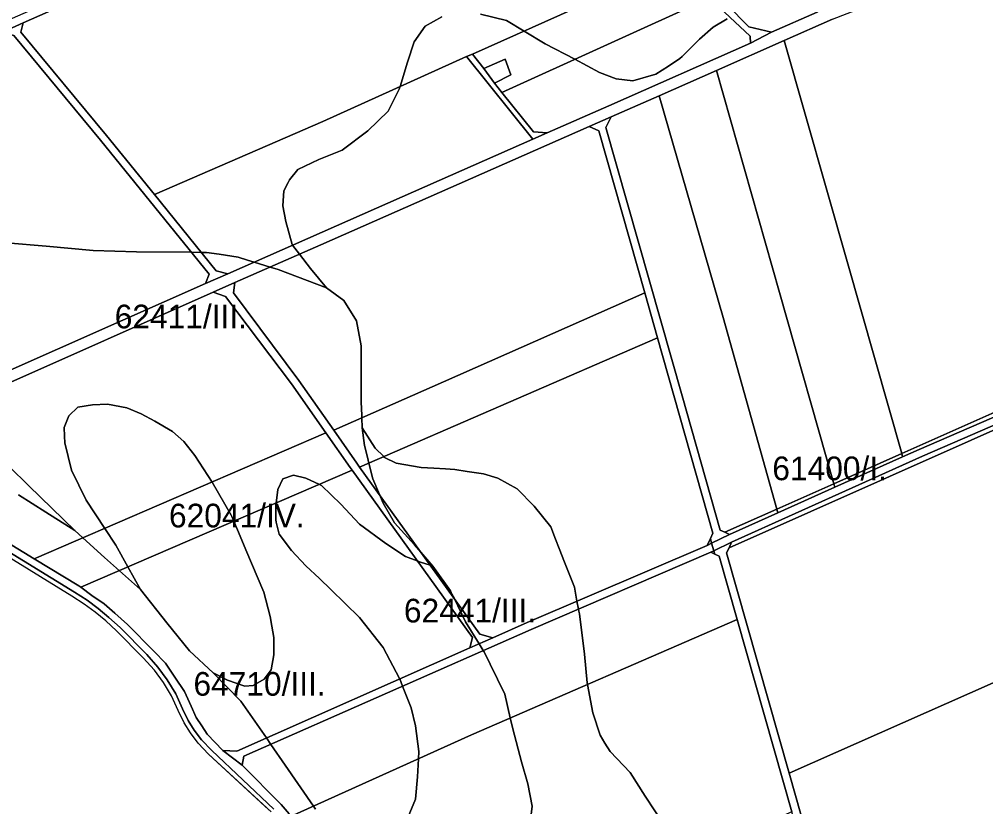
# Model space of a CAD drawing. Extents: x -522079 to -518792, y -1142400 to -1139961.
# Drawn here: x -521597 to -520985, y -1141508 to -1141010 of the extents above; entities that cross this region are included whole.
import ezdxf

# ---------------------------------------------------------------- set-up
doc = ezdxf.new("R2010")
doc.units = 0
for name, color, linetype in [('Hranice parcel', 7, 'Continuous'), ('Parcelní čísla', 7, 'Continuous'), ('Vnitřní kresba', 7, 'Continuous'), ('Značky bodu BP', 7, 'Continuous'), ('Značky budov', 7, 'Continuous')]:
    doc.layers.add(name, color=color, linetype=linetype)

msp = doc.modelspace()

# ---------------------------------------------------------------- linework, layer by layer
at = {"layer": 'Hranice parcel'}
for points in [[(-521134.18, -1141024.63), (-521134.23, -1141020.21), (-521160.03, -1140995.91), (-521180.73, -1140973.62), (-521272.67, -1140872.95), (-521283.24, -1140866.3), (-521275.9, -1140861.47), (-521191.17, -1140957.11), (-521135.25, -1141014.2), (-521120.79, -1141017.67)], [(-521285.67, -1141044.64), (-521296.08, -1141050.04), (-521302.83, -1141040.76), (-521289.36, -1141034.73)], [(-521222.3, -1141071.25), (-521225.53, -1141078.04), (-521177.35, -1141247.92), (-521153.24, -1141332.9), (-521150.33, -1141334.27), (-521147.33, -1141335.67), (-521158.68, -1141341.24), (-521159.51, -1141338.32), (-521157.91, -1141334.94), (-521192.96, -1141211.21), (-521201.01, -1141182.77), (-521230.09, -1141080.11), (-521236.08, -1141077.32)], [(-520895.96, -1141221.04), (-520897.83, -1141225.78), (-521027.41, -1141281.92), (-521037.84, -1141286.59), (-521038.45, -1141284.46)], [(-520893.13, -1141230.74), (-521147.68, -1141344.03), (-521146.08, -1141340.6), (-521025.25, -1141286.2), (-520895.38, -1141229.74)], [(-521037.84, -1141286.59), (-521080.71, -1141305.81), (-521081.35, -1141303.56), (-521038.45, -1141284.46)], [(-521081.35, -1141303.56), (-521080.71, -1141305.81), (-521116.71, -1141321.95), (-521117.38, -1141319.6)], [(-521147.33, -1141335.67), (-521150.33, -1141334.27), (-521117.38, -1141319.6), (-521116.71, -1141321.95)], [(-521147.68, -1141344.03), (-521149.23, -1141347.36), (-521109.72, -1141486.85), (-521084.21, -1141576.91), (-521078.78, -1141596.05), (-521077.42, -1141600.82), (-521086.66, -1141604.9), (-521083.41, -1141598.05), (-521107.96, -1141511.35), (-521142.48, -1141389.44), (-521153.82, -1141349.39), (-521156.76, -1141348.04), (-521157.35, -1141345.97), (-521146.08, -1141340.6)]]:
    msp.add_lwpolyline(points, close=True, dxfattribs=at)
for points in [[(-521082.18, -1141009.47), (-521112.83, -1141022.98), (-521155.63, -1141041.85), (-521191.96, -1141057.88), (-521222.3, -1141071.25), (-521236.08, -1141077.32), (-521405.94, -1141152.24), (-521460.33, -1141176.23), (-521474.13, -1141182.35), (-521609.81, -1141242.59), (-521691.15, -1141278.7), (-521692.02, -1141284.07), (-521705, -1141272.16), (-521696.71, -1141273.51), (-521531.28, -1141200.09), (-521478.81, -1141176.87), (-521464.85, -1141170.68), (-521354.37, -1141121.84), (-521271.86, -1141085.49), (-521262.72, -1141081.47), (-521223.67, -1141064.26), (-521134.18, -1141024.63), (-521120.79, -1141017.67), (-521091.97, -1141005.03)], [(-520895.38, -1141229.74), (-521025.25, -1141286.2), (-521146.08, -1141340.6), (-521157.35, -1141345.97), (-521158.68, -1141341.24), (-521147.33, -1141335.67), (-521116.71, -1141321.95), (-521080.71, -1141305.81), (-521037.84, -1141286.59), (-521027.41, -1141281.92), (-520897.83, -1141225.78)], [(-521604.24, -1141340.75), (-521587.36, -1141351.16), (-521558.92, -1141368.2), (-521557.71, -1141369.1), (-521550.74, -1141374.27), (-521543.06, -1141379.52), (-521536.29, -1141385.49), (-521528.31, -1141392.77), (-521511.47, -1141409.59), (-521504.19, -1141417.07), (-521498.23, -1141425.96), (-521492.17, -1141435.06), (-521488.03, -1141444.36), (-521484.69, -1141451.44), (-521481.18, -1141456.84), (-521477.75, -1141461.99), (-521467.85, -1141472.41), (-521455.62, -1141481.81), (-521431.09, -1141506.63), (-521426.04, -1141512.48)], [(-521435.7, -1141509.5), (-521474.82, -1141472.48), (-521481.44, -1141465.72), (-521485.96, -1141459.56), (-521489.81, -1141453.49), (-521493.43, -1141445.97), (-521497.72, -1141436.55), (-521503.06, -1141427.66), (-521508.94, -1141419.63), (-521516.02, -1141411.74), (-521532.97, -1141394.62), (-521539.97, -1141388.19), (-521546.79, -1141382.47), (-521553.85, -1141377.26), (-521561.83, -1141372.1), (-521608.95, -1141343.32)]]:
    msp.add_lwpolyline(points, dxfattribs=at)
at = {"layer": 'Parcelní čísla'}
for points in [[(-521288.46, -1140863.02), (-521283.24, -1140866.3), (-521272.67, -1140872.95), (-521285.04, -1140873.12), (-521453.3, -1140949.4), (-521594.31, -1141011.83), (-521607.81, -1141017.81), (-521735.67, -1141074.42), (-521844.44, -1141121.41), (-521845.59, -1141127.96), (-521855.85, -1141115.33), (-521847.83, -1141117.27), (-521813.35, -1141102.46), (-521737.51, -1141069.87), (-521612.22, -1141013.76), (-521597.65, -1141007.23), (-521455.15, -1140944.86), (-521289.17, -1140869.28)], [(-521453.3, -1140949.4), (-521285.04, -1140873.12), (-521272.67, -1140872.95), (-521180.73, -1140973.62), (-521309.93, -1141031.69), (-521313.87, -1141033.11), (-521404.59, -1141074.2), (-521511.15, -1141120.5), (-521541.57, -1141083.01), (-521595.68, -1141017.57), (-521594.31, -1141011.83)], [(-520895.4, -1141219.71), (-520895.96, -1141221.04), (-521038.45, -1141284.46), (-521072.62, -1141164.33), (-521112.83, -1141022.98), (-521082.18, -1141009.47), (-521026.59, -1140987.63), (-520970.5, -1140967.09), (-520964.29, -1140970.32), (-520927.66, -1141102.94)], [(-521296.08, -1141050.04), (-521285.67, -1141044.64), (-521289.36, -1141034.73), (-521302.83, -1141040.76), (-521309.93, -1141031.69), (-521180.73, -1140973.62), (-521160.03, -1140995.91), (-521291.39, -1141055.81)], [(-521134.18, -1141024.63), (-521223.67, -1141064.26), (-521262.72, -1141081.47), (-521271.3, -1141080.74), (-521291.39, -1141055.81), (-521160.03, -1140995.91), (-521134.23, -1141020.21)], [(-521464.85, -1141170.68), (-521478.81, -1141176.87), (-521476.67, -1141170.91), (-521545.26, -1141086.06), (-521600.08, -1141019.71), (-521607.81, -1141017.81), (-521594.31, -1141011.83), (-521595.68, -1141017.57), (-521541.57, -1141083.01), (-521511.15, -1141120.5), (-521472.07, -1141168.66)], [(-521705, -1141272.16), (-521746.52, -1141232.38), (-521780.54, -1141201.02), (-521789.46, -1141193.57), (-521801.69, -1141180.84), (-521813.1, -1141167.95), (-521845.59, -1141127.96), (-521844.44, -1141121.41), (-521735.67, -1141074.42), (-521607.81, -1141017.81), (-521600.08, -1141019.71), (-521545.26, -1141086.06), (-521476.67, -1141170.91), (-521478.81, -1141176.87), (-521531.28, -1141200.09), (-521696.71, -1141273.51)], [(-521112.83, -1141022.98), (-521072.62, -1141164.33), (-521038.45, -1141284.46), (-521081.35, -1141303.56), (-521115.71, -1141182.49), (-521155.63, -1141041.85)], [(-521354.37, -1141121.84), (-521464.85, -1141170.68), (-521472.07, -1141168.66), (-521511.15, -1141120.5), (-521404.59, -1141074.2), (-521313.87, -1141033.11), (-521271.86, -1141085.49)], [(-521313.87, -1141033.11), (-521309.93, -1141031.69), (-521302.83, -1141040.76), (-521296.08, -1141050.04), (-521291.39, -1141055.81), (-521271.3, -1141080.74), (-521262.72, -1141081.47), (-521271.86, -1141085.49)], [(-521155.63, -1141041.85), (-521115.71, -1141182.49), (-521081.35, -1141303.56), (-521117.38, -1141319.6), (-521151.45, -1141198.34), (-521191.96, -1141057.88)], [(-521177.35, -1141247.92), (-521225.53, -1141078.04), (-521222.3, -1141071.25), (-521191.96, -1141057.88), (-521151.45, -1141198.34), (-521117.38, -1141319.6), (-521150.33, -1141334.27), (-521153.24, -1141332.9)], [(-521419.75, -1141238.15), (-521461.21, -1141182.74), (-521460.33, -1141176.23), (-521405.94, -1141152.24), (-521236.08, -1141077.32), (-521230.09, -1141080.11), (-521201.01, -1141182.77), (-521328.3, -1141238.94), (-521397.78, -1141269.61)], [(-521474.13, -1141182.35), (-521460.33, -1141176.23), (-521461.21, -1141182.74), (-521419.75, -1141238.15), (-521397.78, -1141269.61), (-521383.22, -1141290.47), (-521381.4, -1141292.99), (-521305.3, -1141398.78), (-521297.15, -1141401.04), (-521311.57, -1141407.43), (-521310.04, -1141400.96), (-521386.12, -1141295.04), (-521387.39, -1141293.27), (-521402.72, -1141271.39), (-521424.55, -1141240.21), (-521466.3, -1141184.96)], [(-521587.36, -1141351.16), (-521604.24, -1141340.75), (-521628.15, -1141324.02), (-521671.77, -1141299.69), (-521692.02, -1141284.07), (-521691.15, -1141278.7), (-521609.81, -1141242.59), (-521474.13, -1141182.35), (-521466.3, -1141184.96), (-521424.55, -1141240.21), (-521402.72, -1141271.39)], [(-521192.96, -1141211.21), (-521381.4, -1141292.99), (-521383.22, -1141290.47), (-521397.78, -1141269.61), (-521328.3, -1141238.94), (-521201.01, -1141182.77)], [(-521157.91, -1141334.94), (-521159.51, -1141338.32), (-521161.56, -1141342.65), (-521275.3, -1141391.36), (-521297.15, -1141401.04), (-521305.3, -1141398.78), (-521381.4, -1141292.99), (-521192.96, -1141211.21)], [(-520851.22, -1141372.34), (-520980.65, -1141429.68), (-521109.72, -1141486.85), (-521149.23, -1141347.36), (-521147.68, -1141344.03), (-520893.13, -1141230.74), (-520889.86, -1141232.13)], [(-521387.39, -1141293.27), (-521386.12, -1141295.04), (-521557.71, -1141369.1), (-521558.92, -1141368.2), (-521587.36, -1141351.16), (-521402.72, -1141271.39)], [(-521386.12, -1141295.04), (-521310.04, -1141400.96), (-521311.57, -1141407.43), (-521459, -1141472.78), (-521467.85, -1141472.41), (-521477.75, -1141461.99), (-521481.18, -1141456.84), (-521484.69, -1141451.44), (-521488.03, -1141444.36), (-521492.17, -1141435.06), (-521498.23, -1141425.96), (-521504.19, -1141417.07), (-521511.47, -1141409.59), (-521528.31, -1141392.77), (-521536.29, -1141385.49), (-521543.06, -1141379.52), (-521550.74, -1141374.27), (-521557.71, -1141369.1)], [(-521161.56, -1141342.65), (-521159.51, -1141338.32), (-521158.68, -1141341.24)], [(-521467.85, -1141472.41), (-521459, -1141472.78), (-521311.57, -1141407.43), (-521297.15, -1141401.04), (-521275.3, -1141391.36), (-521161.56, -1141342.65), (-521158.68, -1141341.24), (-521157.35, -1141345.97), (-521159.26, -1141346.88), (-521272.96, -1141395.84), (-521454.54, -1141476.12), (-521455.62, -1141481.81)], [(-521431.09, -1141506.63), (-521455.62, -1141481.81), (-521454.54, -1141476.12), (-521272.96, -1141395.84), (-521159.26, -1141346.88), (-521156.76, -1141348.04), (-521153.82, -1141349.39), (-521142.48, -1141389.44), (-521310.56, -1141462.49), (-521425.07, -1141514.17), (-521426.04, -1141512.48)], [(-521156.76, -1141348.04), (-521159.26, -1141346.88), (-521157.35, -1141345.97)], [(-521378.39, -1141629.5), (-521389.3, -1141621.72), (-521393.54, -1141617.98), (-521399.61, -1141612.42), (-521404.05, -1141606.86), (-521406.05, -1141602.85), (-521409.49, -1141593.05), (-521412.01, -1141585.06), (-521414.13, -1141574.69), (-521415.34, -1141566.3), (-521417.47, -1141538.2), (-521418.07, -1141529.55), (-521421, -1141521.26), (-521425.07, -1141514.17), (-521310.56, -1141462.49), (-521142.48, -1141389.44), (-521107.96, -1141511.35), (-521234.07, -1141566.44)], [(-520980.65, -1141429.68), (-520955.18, -1141519.6), (-521084.21, -1141576.91), (-521109.72, -1141486.85)]]:
    msp.add_lwpolyline(points, close=True, dxfattribs=at)
at = {"layer": 'Vnitřní kresba'}
for points in [[(-521437.41, -1141511.31), (-521476.9, -1141474.65), (-521483.59, -1141467.79), (-521488.42, -1141461.33), (-521492.43, -1141454.93), (-521496.24, -1141447.12), (-521500.39, -1141437.89), (-521505.54, -1141429.29), (-521511.22, -1141421.52), (-521518.22, -1141413.8), (-521535.13, -1141396.73), (-521541.97, -1141390.39), (-521548.66, -1141384.81), (-521555.61, -1141379.71), (-521563.41, -1141374.64), (-521610.54, -1141345.88)], [(-521608.95, -1141343.32), (-521561.83, -1141372.1), (-521553.85, -1141377.26), (-521546.79, -1141382.47), (-521539.97, -1141388.19), (-521532.97, -1141394.62), (-521516.02, -1141411.74), (-521508.94, -1141419.63), (-521503.06, -1141427.66), (-521497.72, -1141436.55), (-521493.43, -1141445.97), (-521489.81, -1141453.49), (-521485.96, -1141459.56), (-521481.44, -1141465.72), (-521474.82, -1141472.48), (-521435.7, -1141509.5)]]:
    msp.add_lwpolyline(points, dxfattribs=at)
at = {"layer": 'Značky bodu BP'}
for points in [[(-521329.43, -1141007.98), (-521339.94, -1141013.83), (-521346.95, -1141023.8), (-521351.04, -1141036.69), (-521355.81, -1141052.1), (-521356.3, -1141053.68), (-521363.31, -1141067.75), (-521376.16, -1141080.05), (-521392.52, -1141092.36), (-521407.12, -1141098.22), (-521420.56, -1141104.67), (-521425.81, -1141111.11), (-521426.69, -1141112.87), (-521429.32, -1141118.14), (-521429.9, -1141127.52), (-521428.15, -1141137.48), (-521424.06, -1141152.13), (-521423.76, -1141152.52), (-521419.42, -1141158.18), (-521412.38, -1141167.36), (-521402.29, -1141179.6), (-521432.87, -1141168.01), (-521438.03, -1141166.39), (-521448.04, -1141163.25), (-521452.23, -1141161.94), (-521458.24, -1141160.06), (-521470.15, -1141158.29), (-521478.17, -1141157.1), (-521479.52, -1141157.09), (-521481.47, -1141157.07), (-521487.91, -1141157), (-521522.57, -1141156.65), (-521549.98, -1141155.96), (-521579.71, -1141153.25), (-521604.79, -1141150.97)], [(-521188.48, -1141519.97), (-521200.71, -1141501.34), (-521210.22, -1141486.34), (-521222.9, -1141473.16), (-521226.22, -1141467.7), (-521229.25, -1141462.71), (-521233.78, -1141448.62), (-521237.2, -1141430.6), (-521237.4, -1141429.53), (-521239.21, -1141411.36), (-521242.38, -1141385.91), (-521242.72, -1141384.12), (-521242.95, -1141382.92), (-521243.89, -1141377.91), (-521245.55, -1141369.09), (-521251.72, -1141353.18), (-521255.07, -1141344.56), (-521257.4, -1141338.72), (-521260.5, -1141330.92), (-521270.92, -1141317.75), (-521281.8, -1141306.84), (-521294.03, -1141300.02), (-521303.09, -1141297.29), (-521313.39, -1141295.74), (-521321.21, -1141294.57), (-521327.01, -1141294.2), (-521334.39, -1141293.72), (-521342.5, -1141293.2), (-521358.35, -1141290.48), (-521365.6, -1141286.84), (-521366.09, -1141286.35), (-521371.49, -1141280.93), (-521379.87, -1141268.21), (-521380.05, -1141261.78), (-521380.06, -1141261.15), (-521380.08, -1141260.38), (-521380.32, -1141251.62), (-521380.32, -1141230.49), (-521380.32, -1141216.18), (-521383.27, -1141200.5), (-521391.42, -1141187.55), (-521402.29, -1141179.6), (-521412.38, -1141167.36), (-521419.42, -1141158.18), (-521423.76, -1141152.52), (-521424.06, -1141152.13), (-521428.15, -1141137.48), (-521429.9, -1141127.52), (-521429.32, -1141118.14), (-521426.69, -1141112.87), (-521425.81, -1141111.11), (-521420.56, -1141104.67), (-521407.12, -1141098.22), (-521392.52, -1141092.36), (-521376.16, -1141080.05), (-521363.31, -1141067.75), (-521356.3, -1141053.68), (-521355.81, -1141052.1), (-521351.04, -1141036.69), (-521346.95, -1141023.8), (-521339.94, -1141013.83), (-521329.43, -1141007.98)], [(-521148.92, -1141009.15), (-521157.69, -1141014.42), (-521166.45, -1141022.04), (-521177.36, -1141032.99), (-521178.72, -1141034.34), (-521186.08, -1141039.18), (-521193.9, -1141044.31), (-521208.51, -1141048.41), (-521219.02, -1141047.24), (-521229.54, -1141043.13), (-521245.33, -1141034.81), (-521264, -1141024.97), (-521277.31, -1141017.02), (-521288.54, -1141010.32), (-521304.89, -1141006.22)], [(-521304.89, -1141006.22), (-521288.54, -1141010.32), (-521277.31, -1141017.02), (-521264, -1141024.97), (-521245.33, -1141034.81), (-521229.54, -1141043.13), (-521219.02, -1141047.24), (-521208.51, -1141048.41), (-521193.9, -1141044.31), (-521186.08, -1141039.18), (-521178.72, -1141034.34), (-521177.36, -1141032.99), (-521166.45, -1141022.04), (-521157.69, -1141014.42), (-521148.92, -1141009.15)], [(-521604.79, -1141150.97), (-521579.71, -1141153.25), (-521549.98, -1141155.96), (-521522.57, -1141156.65), (-521487.91, -1141157), (-521481.47, -1141157.07), (-521479.52, -1141157.09), (-521478.17, -1141157.1), (-521470.15, -1141158.29), (-521458.24, -1141160.06), (-521452.23, -1141161.94), (-521448.04, -1141163.25), (-521438.03, -1141166.39), (-521432.87, -1141168.01), (-521402.29, -1141179.6), (-521391.42, -1141187.55), (-521383.27, -1141200.5), (-521380.32, -1141216.18), (-521380.32, -1141230.49), (-521380.32, -1141251.62), (-521380.08, -1141260.38), (-521380.06, -1141261.15), (-521380.05, -1141261.78), (-521379.87, -1141268.21), (-521378.28, -1141279.34), (-521376.46, -1141286.74), (-521375.55, -1141290.45), (-521373.08, -1141300.48), (-521368.83, -1141310.46), (-521366.51, -1141315.93), (-521359.26, -1141328.2), (-521346.57, -1141342.28), (-521342.67, -1141346.82), (-521335.08, -1141355.66), (-521336.68, -1141355.16), (-521342.95, -1141353.19), (-521344.88, -1141352.45), (-521352.46, -1141349.55), (-521364.7, -1141341.37), (-521381.46, -1141329.1), (-521393.24, -1141316.38), (-521405.47, -1141304.57), (-521406.27, -1141304.2), (-521406.79, -1141303.96), (-521415.43, -1141300.02), (-521423.13, -1141298.2), (-521429.93, -1141300.48), (-521433.1, -1141307.29), (-521434.26, -1141315.82), (-521434.46, -1141317.29), (-521434.46, -1141326.38), (-521434.1, -1141327.81), (-521432.19, -1141335.47), (-521424.49, -1141345.92), (-521415.43, -1141355.46), (-521406.81, -1141363.62), (-521399.58, -1141370.46), (-521381.46, -1141388.18), (-521366.51, -1141407.27), (-521356.09, -1141426.81), (-521355.97, -1141427.11), (-521354.17, -1141431.74), (-521348.84, -1141445.44), (-521346.12, -1141456.8), (-521343.86, -1141473.16), (-521344.11, -1141477.63), (-521344.76, -1141489.07), (-521346.12, -1141503.16), (-521350.65, -1141514.51)], [(-521409.25, -1141509.65), (-521410.62, -1141507.65), (-521428.44, -1141481.62), (-521437.49, -1141468.58), (-521440.32, -1141464.5), (-521456.46, -1141441.25), (-521474, -1141423.33), (-521465, -1141428.01), (-521454, -1141431.68), (-521448.67, -1141431.35), (-521441.67, -1141427.34), (-521437.34, -1141421.32), (-521435.67, -1141411.96), (-521435.67, -1141400.93), (-521436.94, -1141393.68), (-521438.01, -1141387.56), (-521442.01, -1141372.18), (-521453.34, -1141345.44), (-521456.99, -1141336.81), (-521460.98, -1141327.35), (-521462.31, -1141324.22), (-521462.67, -1141323.37), (-521474.66, -1141302.65), (-521474.75, -1141302.51), (-521485.66, -1141285.6), (-521492.66, -1141276.91), (-521499.66, -1141270.55), (-521510.99, -1141263.87), (-521519.65, -1141259.19), (-521528.65, -1141255.51), (-521540.98, -1141253.17), (-521550.31, -1141253.51), (-521559.64, -1141255.18), (-521565.31, -1141260.52), (-521568.31, -1141267.88), (-521568.11, -1141273.46), (-521567.97, -1141277.58), (-521563.64, -1141294.96), (-521554.31, -1141314.01), (-521542.61, -1141331.83), (-521535.65, -1141342.43), (-521527.94, -1141356.25), (-521519.98, -1141370.51), (-521533.36, -1141358.59), (-521542.73, -1141350.24), (-521556.45, -1141337.8), (-521561.53, -1141333.19), (-521590.75, -1141304.79), (-521615.66, -1141280.48)], [(-521274.09, -1141523.6), (-521272.28, -1141507.7), (-521275, -1141493.61), (-521279.08, -1141479.52), (-521284.51, -1141458.62), (-521286.06, -1141451.84), (-521289.5, -1141436.81), (-521298.8, -1141417.81), (-521302.63, -1141410), (-521303.14, -1141409.18), (-521305.8, -1141404.87), (-521314.41, -1141390.91), (-521321.64, -1141376.07), (-521322.95, -1141373.36), (-521323.92, -1141371.37), (-521335.08, -1141355.66), (-521342.67, -1141346.82), (-521346.57, -1141342.28), (-521359.26, -1141328.2), (-521366.51, -1141315.93), (-521368.83, -1141310.46), (-521373.08, -1141300.48), (-521375.55, -1141290.45), (-521376.46, -1141286.74), (-521378.28, -1141279.34), (-521379.87, -1141268.21), (-521371.49, -1141280.93), (-521366.09, -1141286.35), (-521365.6, -1141286.84), (-521358.35, -1141290.48), (-521342.5, -1141293.2), (-521334.39, -1141293.72), (-521327.01, -1141294.2), (-521321.21, -1141294.57), (-521313.39, -1141295.74), (-521303.09, -1141297.29), (-521294.03, -1141300.02), (-521281.8, -1141306.84), (-521270.92, -1141317.75), (-521260.5, -1141330.92), (-521257.4, -1141338.72), (-521255.07, -1141344.56), (-521251.72, -1141353.18), (-521245.55, -1141369.09), (-521243.89, -1141377.91), (-521242.95, -1141382.92), (-521242.72, -1141384.12), (-521242.38, -1141385.91), (-521239.21, -1141411.36), (-521237.4, -1141429.53), (-521237.2, -1141430.6), (-521233.78, -1141448.62), (-521229.25, -1141462.71), (-521226.22, -1141467.7), (-521222.9, -1141473.16), (-521210.22, -1141486.34), (-521200.71, -1141501.34), (-521188.48, -1141519.97)], [(-521615.66, -1141280.48), (-521590.75, -1141304.79), (-521561.53, -1141333.19), (-521579.88, -1141321.61), (-521597.19, -1141310.6)], [(-521350.65, -1141514.51), (-521346.12, -1141503.16), (-521344.76, -1141489.07), (-521344.11, -1141477.63), (-521343.86, -1141473.16), (-521346.12, -1141456.8), (-521348.84, -1141445.44), (-521354.17, -1141431.74), (-521355.97, -1141427.11), (-521356.09, -1141426.81), (-521366.51, -1141407.27), (-521381.46, -1141388.18), (-521399.58, -1141370.46), (-521406.81, -1141363.62), (-521415.43, -1141355.46), (-521424.49, -1141345.92), (-521432.19, -1141335.47), (-521434.1, -1141327.81), (-521434.46, -1141326.38), (-521434.46, -1141317.29), (-521434.26, -1141315.82), (-521433.1, -1141307.29), (-521429.93, -1141300.48), (-521423.13, -1141298.2), (-521415.43, -1141300.02), (-521406.79, -1141303.96), (-521406.27, -1141304.2), (-521405.47, -1141304.57), (-521393.24, -1141316.38), (-521381.46, -1141329.1), (-521364.7, -1141341.37), (-521352.46, -1141349.55), (-521344.88, -1141352.45), (-521342.95, -1141353.19), (-521336.68, -1141355.16), (-521335.08, -1141355.66), (-521323.92, -1141371.37), (-521322.95, -1141373.36), (-521321.64, -1141376.07), (-521314.41, -1141390.91), (-521305.8, -1141404.87), (-521303.14, -1141409.18), (-521302.63, -1141410), (-521298.8, -1141417.81), (-521289.5, -1141436.81), (-521286.06, -1141451.84), (-521284.51, -1141458.62), (-521279.08, -1141479.52), (-521275, -1141493.61), (-521272.28, -1141507.7), (-521274.09, -1141523.6)], [(-521597.19, -1141310.6), (-521579.88, -1141321.61), (-521561.53, -1141333.19), (-521556.45, -1141337.8), (-521542.73, -1141350.24), (-521533.36, -1141358.59), (-521519.98, -1141370.51), (-521503.32, -1141391.57), (-521488.99, -1141409.29), (-521474, -1141423.33), (-521456.46, -1141441.25), (-521440.32, -1141464.5), (-521437.49, -1141468.58), (-521428.44, -1141481.62), (-521410.62, -1141507.65), (-521409.25, -1141509.65)], [(-521437.41, -1141511.31), (-521441.06, -1141507.92), (-521476.9, -1141474.65), (-521483.59, -1141467.79), (-521488.42, -1141461.33), (-521492.43, -1141454.93), (-521496.24, -1141447.12), (-521500.39, -1141437.89), (-521505.54, -1141429.29), (-521511.22, -1141421.52), (-521518.22, -1141413.8), (-521535.13, -1141396.73), (-521541.97, -1141390.39), (-521548.66, -1141384.81), (-521555.61, -1141379.71), (-521563.41, -1141374.64), (-521610.54, -1141345.88)]]:
    msp.add_lwpolyline(points, dxfattribs=at)
msp.add_lwpolyline([(-521448.67, -1141431.35), (-521454, -1141431.68), (-521465, -1141428.01), (-521474, -1141423.33), (-521488.99, -1141409.29), (-521503.32, -1141391.57), (-521519.98, -1141370.51), (-521527.94, -1141356.25), (-521535.65, -1141342.43), (-521542.61, -1141331.83), (-521554.31, -1141314.01), (-521563.64, -1141294.96), (-521567.97, -1141277.58), (-521568.11, -1141273.46), (-521568.31, -1141267.88), (-521565.31, -1141260.52), (-521559.64, -1141255.18), (-521550.31, -1141253.51), (-521540.98, -1141253.17), (-521528.65, -1141255.51), (-521519.65, -1141259.19), (-521510.99, -1141263.87), (-521499.66, -1141270.55), (-521492.66, -1141276.91), (-521485.66, -1141285.6), (-521474.75, -1141302.51), (-521474.66, -1141302.65), (-521462.67, -1141323.37), (-521462.31, -1141324.22), (-521460.98, -1141327.35), (-521456.99, -1141336.81), (-521453.34, -1141345.44), (-521442.01, -1141372.18), (-521438.01, -1141387.56), (-521436.94, -1141393.68), (-521435.67, -1141400.93), (-521435.67, -1141411.96), (-521437.34, -1141421.32), (-521441.67, -1141427.34)], close=True, dxfattribs=at)
at = {"layer": 'Značky budov'}
msp.add_lwpolyline([(-521283.37, -1140860.94), (-521307.86, -1140833.61), (-521298.55, -1140826.47), (-521220.23, -1140832.37), (-521184.18, -1140870.5), (-521185.72, -1140871.68), (-521143.12, -1140927.46), (-521088.9, -1141000.66), (-521091.97, -1141005.03), (-521120.79, -1141017.67), (-521135.25, -1141014.2), (-521191.17, -1140957.11), (-521275.9, -1140861.47), (-521279.53, -1140861.89)], close=True, dxfattribs=at)

# ---------------------------------------------------------------- texts
at = {"layer": 'Značky bodu BP'}
for s, rotation, p in [('62411/III.', 360, (-521536.3, -1141205.18)), ('61400/I.', 0, (-521120.3, -1141301.32)), ('62041/IV.', 0, (-521501.99, -1141331.2)), ('62441/III.', 360, (-521353.37, -1141391.37)), ('64710/III.', 360, (-521486.5, -1141437.75))]:
    msp.add_text(s, height=15, rotation=rotation, dxfattribs=at).set_placement(p)

doc.saveas('drawing.dxf')
